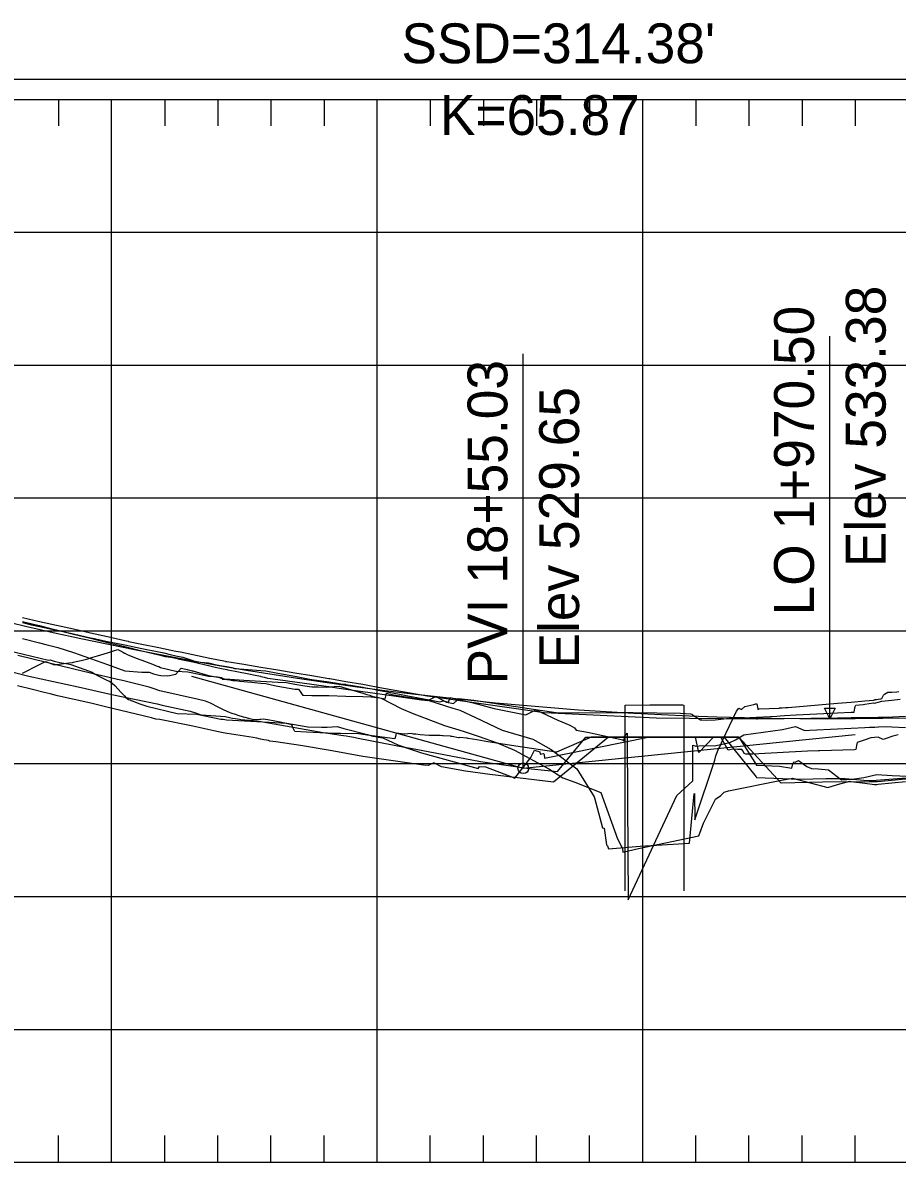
# Model space of a CAD drawing. Extents: x 704834 to 709892, y 372981 to 377533.
# Drawn here: x 706867 to 707196.3, y 375272.4 to 375701.3 of the extents above; entities that cross this region are included whole.
import ezdxf

# ---------------------------------------------------------------- set-up
doc = ezdxf.new("R2010")
doc.units = 0
for name, color, linetype in [('1', 7, 'Continuous'), ('10', 7, 'Continuous'), ('12', 7, 'Continuous'), ('13', 7, 'Continuous'), ('20', 7, 'Continuous'), ('42', 7, 'Continuous'), ('49', 7, 'Continuous'), ('59', 7, 'Continuous'), ('61', 7, 'Continuous'), ('63', 7, 'Continuous'), ('Default_Profile', 7, 'Continuous'), ('Existing', 7, 'Continuous')]:
    doc.layers.add(name, color=color, linetype=linetype)

msp = doc.modelspace()

# ---------------------------------------------------------------- linework, layer by layer
at = {"layer": '1'}
for p, q in [((706930.44, 375455.38), (707055.44, 375420.71)), ((707055.44, 375420.71), (707180.44, 375433.47))]:
    msp.add_line(p, q, dxfattribs=at)
at = {"layer": '10'}
for points in [[(706860.99, 375465.14), (706876.59, 375461.44), (706877.24, 375461.49), (706878.79, 375460.97), (706880.89, 375460.48), (706883.98, 375460.02), (706885.07, 375459.78), (706893.13, 375456.84), (706894.01, 375456.3), (706895.56, 375455.39), (706897.16, 375454.57), (706898.85, 375453.8), (706899.66, 375453.49), (706900.6, 375452.8), (706900.61, 375452.8), (706901.6, 375451.83), (706901.73, 375451.71), (706902.73, 375450.65), (706902.91, 375450.48), (706903.89, 375449.38), (706904.6, 375448.57), (706905.23, 375448.01), (706905.8, 375447.39), (706906.76, 375446.58), (706907.37, 375446.41), (706907.76, 375446.25), (706908.19, 375446.06), (706911.08, 375445.01), (706913.73, 375444.04), (706925.13, 375441.35), (706932.54, 375441.02), (706941.51, 375439.24), (706941.75, 375439.15), (706942.48, 375439.15), (706943.64, 375438.96), (706966.39, 375437.68), (706974.29, 375436.35), (706974.38, 375436.33), (706979.42, 375436.2), (706981.63, 375436.12), (706985.3, 375436.46), (706987.8, 375435.69), (706996.74, 375433.37), (706997.63, 375433.2), (706998.28, 375432.94), (706998.8, 375432.82), (706999.76, 375432.68), (707000.74, 375432.44), (707002.51, 375432.11), (707008.22, 375429.47), (707013.76, 375427.63), (707017.09, 375426.56), (707029.47, 375423.1), (707034.29, 375421.8), (707038.41, 375420.66), (707038.9, 375421.43), (707041.21, 375421.24), (707050.73, 375417.58), (707052.3, 375416.96), (707058.28, 375424.76), (707059.63, 375427.58), (707061.63, 375426.91), (707061.8, 375426.02), (707063.06, 375426.25), (707063.2, 375426.13), (707063.3, 375425.92), (707063.45, 375424.53), (707102.5, 375432.45), (707136.6, 375432.45), (707143.22, 375421.86), (707151.88, 375421.55), (707156.51, 375420.78), (707156.9, 375422.41), (707157.31, 375423.1), (707157.86, 375423), (707159.13, 375423.61), (707162.21, 375421.35), (707163.94, 375420.6), (707166.48, 375420.52), (707170.37, 375420.1), (707175.25, 375416.32), (707179.3, 375416.66), (707183.63, 375417.26), (707188.52, 375418.39), (707194.35, 375417.95), (707211.49, 375417.2)], [(707196.62, 375433.32), (707194.65, 375432.74), (707191.76, 375431.83), (707190.91, 375431.58), (707189.06, 375432.41), (707186.36, 375432.18), (707183.84, 375431.31), (707181.2, 375430.39), (707180.98, 375429.29), (707180.69, 375427.81), (707180.11, 375427.59), (707167.08, 375427.3), (707166.56, 375427.29), (707162.41, 375427.16), (707141.92, 375426.06), (707139.28, 375425.98), (707138.62, 375426.23), (707138.57, 375426.25), (707138.26, 375427.13), (707137.75, 375427.76), (707136.23, 375427.82), (707134.77, 375427.84), (707134.33, 375427.85), (707133.22, 375427.67), (707132.59, 375427.57), (707129.8, 375432.45), (707129.25, 375432.45), (707128.72, 375432.45), (707128.22, 375432.45), (707127.85, 375432.45), (707127.75, 375432.45), (707127.06, 375432.45), (707121.61, 375426.67), (707120.24, 375432.45), (707118.71, 375432.45), (707117.99, 375432.45), (707117.26, 375432.45), (707115.06, 375432.45), (707105.53, 375432.45), (707090.9, 375432.45), (707081.04, 375432.45), (707067.91, 375426.8), (707067.86, 375426.8), (707052.68, 375429.08), (707041.35, 375430.8), (707040.76, 375430.89), (707037.99, 375431.39), (707034.7, 375431.95), (707034.61, 375431.96), (707034.37, 375432), (707031.42, 375432.29), (707031.19, 375432.11), (707031.05, 375432.12), (707028.68, 375432.67), (707028.33, 375432.7), (707028.05, 375432.74), (707025.3, 375432.88), (707025.17, 375432.9), (707025.08, 375432.92), (707024.13, 375433.01), (707023.75, 375433.01), (707022.18, 375433.02), (707022.07, 375433.02), (707020.01, 375433.03), (707016.59, 375433.35), (707015.01, 375433.52), (707014.11, 375433.6), (707013.24, 375433.76), (707010.72, 375433.58), (707010.54, 375433.58), (707007.62, 375433.94), (707007.27, 375432.66), (707007.01, 375431.85), (706996.65, 375433.19), (706993.36, 375433.62), (706986.56, 375433.76), (706985.89, 375433.75), (706984.97, 375433.76), (706983.66, 375433.79), (706981.76, 375433.87), (706978.82, 375434), (706973.82, 375434.26), (706969.39, 375434.5), (706969.12, 375435.11), (706968.79, 375435.75), (706968.32, 375437.01), (706964.56, 375437.89), (706959.3, 375438.92), (706957.47, 375439.13), (706956.61, 375439.12), (706956.28, 375439.11), (706953.98, 375438.95), (706953.45, 375439.06), (706952.93, 375439.23), (706950.74, 375439.76), (706950.14, 375439.98), (706948.11, 375440.55), (706947.46, 375440.8), (706945.48, 375441.44), (706944.81, 375441.72), (706942.77, 375442.61), (706940.49, 375443.7), (706937.7, 375445.19), (706935.83, 375445.99), (706933.19, 375446.53), (706918.54, 375449.9), (706917.77, 375450.13), (706916.77, 375450.49), (706914.6, 375451.21), (706904.52, 375453.76), (706902.65, 375454.17), (706899.43, 375454.82), (706895.09, 375455.85), (706886.22, 375457.98), (706865.07, 375463.11)]]:
    msp.add_lwpolyline(points, dxfattribs=at)
at = {"layer": '12'}
msp.add_lwpolyline([(706851.88, 375459.74), (706869.18, 375455.39), (706887.84, 375451.35), (706900.49, 375448.46), (706917.52, 375444.97), (706919.45, 375444.47), (706929.96, 375442.21), (706932.06, 375441.52), (706934.06, 375440.81), (706934.28, 375440.8), (706943.22, 375440.18), (706944.76, 375439.82), (706945.95, 375439.59), (706946.96, 375439.42), (706947.81, 375439.29), (706948.52, 375439.15), (706949.11, 375439.01), (706955.26, 375438.58), (706980.03, 375434.14), (706985.24, 375433.37), (706985.93, 375433.29), (706986.75, 375433.18), (706987.69, 375433.03), (706988.78, 375432.86), (706990.08, 375432.63), (706991.57, 375432.36), (706993.27, 375432.04), (707010.71, 375428.7), (707012.24, 375428.41), (707014.41, 375428), (707025.52, 375425.9), (707039.29, 375423.27), (707049.88, 375421.8), (707058.5, 375420.54), (707068.33, 375419.53), (707079.04, 375432.45), (707079.91, 375432.45), (707102.93, 375432.45), (707104.7, 375432.45), (707131.11, 375432.45), (707143.08, 375417.46), (707143.29, 375417.29), (707159.6, 375416.64), (707169.37, 375416.85), (707176.5, 375416.89), (707176.64, 375416.89), (707183.63, 375416.18), (707186.7, 375416.1), (707209.3, 375417.89)], dxfattribs=at)
at = {"layer": '13'}
msp.add_lwpolyline([(707204.83, 375417.14), (707188.84, 375415.61), (707185.75, 375415.59), (707168.16, 375415.48), (707152.53, 375415.06), (707136.61, 375432.45), (707128.3, 375432.45), (707118.97, 375432.45), (707114.72, 375432.45), (707113.37, 375432.45), (707107.84, 375432.45), (707095.85, 375432.45), (707087.51, 375432.45), (707066.87, 375415.54), (707042.89, 375418.32), (707033.69, 375419.65), (707024.67, 375421.24), (707021.72, 375422.74), (707019.57, 375421.73), (707017.9, 375421.89), (706994.96, 375425.2), (706982.69, 375427.36), (706971.49, 375429.29), (706962.28, 375430.65), (706960.01, 375430.94), (706959.44, 375431.1), (706958.7, 375431.26), (706957.69, 375431.47), (706956.46, 375431.71), (706955.09, 375431.98), (706953.71, 375432.26), (706943.92, 375433.76), (706942.36, 375434.1), (706940.71, 375434.47), (706938.92, 375434.86), (706931.04, 375436.58), (706918.59, 375439.01), (706917.04, 375439.2), (706915.42, 375439.63), (706898.08, 375443.83), (706892.65, 375445.18), (706880.07, 375447.95), (706877.23, 375448.68), (706875.04, 375449.24), (706870.1, 375450.5), (706864.99, 375451.78)], dxfattribs=at)
at = {"layer": '42'}
for p, q in [((707170.9, 375439.37), (707170.9, 375583.37)), ((707055.44, 375420.71), (707055.44, 375576.71))]:
    msp.add_line(p, q, dxfattribs=at)
for points in [[(706819.3, 375680.05), (707291.58, 375680.05)], [(706857.52, 375476.64), (706867.94, 375474.2), (706878.35, 375471.85), (706888.77, 375469.57), (706899.19, 375467.38), (706909.6, 375465.28), (706920.02, 375463.25), (706930.44, 375461.31), (706940.85, 375459.45), (706951.27, 375457.67), (706961.69, 375455.98), (706972.1, 375454.36), (706982.52, 375452.83), (706992.94, 375451.39), (707003.35, 375450.02), (707013.77, 375448.74), (707024.19, 375447.54), (707034.6, 375446.42), (707045.02, 375445.38), (707065.85, 375443.55), (707076.27, 375442.76), (707086.69, 375442.06), (707097.1, 375441.43), (707107.52, 375440.89), (707117.94, 375440.43), (707128.35, 375440.05), (707138.77, 375439.76), (707149.19, 375439.55), (707159.6, 375439.42), (707170.02, 375439.37), (707180.44, 375439.4), (707190.85, 375439.52), (707201.27, 375439.72)]]:
    msp.add_lwpolyline(points, dxfattribs=at)
msp.add_lwpolyline([(707170.9, 375439.37), (707168.9, 375443.37), (707172.9, 375443.37)], close=True, dxfattribs=at)
msp.add_circle((707055.44, 375420.71), 2, dxfattribs=at)
at = {"layer": '59'}
msp.add_lwpolyline([(707093.82, 375374.52), (707093.83, 375425.31), (707093.84, 375444.52), (707103.12, 375444.61), (707104.84, 375444.62), (707115.44, 375444.53), (707115.8, 375444.52), (707115.85, 375444.52), (707115.85, 375444.16), (707115.87, 375374.52)], dxfattribs=at)
at = {"layer": '61'}
for p, q in [((706700.4, 375672.45), (709300.4, 375672.45)), ((706880.4, 375672.45), (706880.4, 375662.45)), ((706900.4, 375272.45), (706900.4, 375672.45)), ((706920.4, 375672.45), (706920.4, 375662.45)), ((706940.4, 375672.45), (706940.4, 375662.45)), ((706960.4, 375672.45), (706960.4, 375662.45)), ((706980.4, 375672.45), (706980.4, 375662.45)), ((707000.4, 375272.45), (707000.4, 375672.45)), ((707020.4, 375672.45), (707020.4, 375662.45)), ((707040.4, 375672.45), (707040.4, 375662.45)), ((707060.4, 375672.45), (707060.4, 375662.45)), ((707080.4, 375672.45), (707080.4, 375662.45)), ((707100.4, 375272.45), (707100.4, 375672.45)), ((707120.4, 375672.45), (707120.4, 375662.45)), ((707140.4, 375672.45), (707140.4, 375662.45)), ((707160.4, 375672.45), (707160.4, 375662.45)), ((707180.4, 375672.45), (707180.4, 375662.45)), ((706700.4, 375622.45), (709300.4, 375622.45)), ((706700.4, 375572.45), (709300.4, 375572.45)), ((706700.4, 375522.45), (709300.4, 375522.45)), ((706700.4, 375472.45), (709300.4, 375472.45)), ((706700.4, 375422.45), (709300.4, 375422.45)), ((706700.4, 375372.45), (709300.4, 375372.45)), ((706700.4, 375322.45), (709300.4, 375322.45)), ((706880.4, 375272.45), (706880.4, 375282.45)), ((706920.4, 375272.45), (706920.4, 375282.45)), ((706940.4, 375272.45), (706940.4, 375282.45)), ((706960.4, 375272.45), (706960.4, 375282.45)), ((706980.4, 375272.45), (706980.4, 375282.45)), ((707020.4, 375272.45), (707020.4, 375282.45)), ((707040.4, 375272.45), (707040.4, 375282.45)), ((707060.4, 375272.45), (707060.4, 375282.45)), ((707080.4, 375272.45), (707080.4, 375282.45)), ((707120.4, 375272.45), (707120.4, 375282.45)), ((707140.4, 375272.45), (707140.4, 375282.45)), ((707160.4, 375272.45), (707160.4, 375282.45)), ((707180.4, 375272.45), (707180.4, 375282.45)), ((706700.4, 375272.45), (709300.4, 375272.45))]:
    msp.add_line(p, q, dxfattribs=at)
at = {"layer": '63'}
for points in [[(706866.88, 375476.01), (706871.47, 375474.86), (706873.29, 375474.39), (706877.95, 375473.19), (706879.7, 375472.75), (706884.58, 375471.5), (706886.1, 375471.16), (706888.23, 375470.7), (706892.51, 375469.63), (706895.29, 375468.94), (706898.92, 375468.06), (706905.33, 375466.51), (706911.74, 375464.95), (706918.14, 375463.39), (706918.29, 375463.35), (706920.52, 375462.76), (706922.66, 375462.49), (706924.55, 375462.11), (706925.94, 375461.83), (706930.96, 375460.72), (706936.9, 375459.38), (706937.37, 375459.28), (706939.46, 375458.81), (706941.85, 375458.27), (706943.78, 375457.84), (706944.14, 375457.75), (706946.89, 375457.31), (706949.46, 375456.78), (706950.18, 375456.63), (706952.06, 375456.24), (706954.45, 375455.75), (706956.44, 375455.33), (706956.59, 375455.29), (706957.92, 375454.97), (706959.08, 375454.64), (706963, 375454.1), (706969.41, 375453.22), (706975.81, 375452.33), (706982.03, 375451.45), (706982.22, 375451.42), (706982.73, 375451.34), (706983.57, 375451.19), (706988.63, 375450.49), (706995.04, 375449.6), (707001.45, 375448.71), (707017.1, 375446.46), (707019.45, 375446.23), (707022.45, 375447.66), (707026.56, 375445.57), (707029.12, 375445.12), (707030.46, 375446.18), (707031.04, 375446.92), (707036.8, 375446.35), (707037.72, 375446.23), (707039.32, 375445.98), (707061.82, 375442.57), (707067.85, 375441.66), (707067.87, 375441.66), (707072.88, 375441.58), (707092.7, 375441.7), (707096.87, 375441.74), (707114.69, 375441.49), (707118.39, 375441.26), (707118.76, 375441.1), (707118.88, 375441.06), (707119.19, 375440.88), (707122.15, 375438.99), (707122.73, 375438.95), (707124.55, 375438.79), (707127.75, 375438.99), (707133.06, 375439.53), (707140.78, 375439.84), (707150.86, 375440.36), (707152.21, 375440.48), (707153.8, 375440.55), (707158.25, 375440.85), (707173.76, 375441.58), (707178.88, 375441.82), (707179.03, 375441.83), (707179.98, 375441.86), (707180.26, 375443.28), (707180.45, 375443.96), (707180.62, 375444.44), (707183.42, 375444.73), (707184, 375444.82), (707187.35, 375445.28), (707187.57, 375445.2), (707188.21, 375445.4), (707189.12, 375445.61), (707190.52, 375445.94), (707194.24, 375446.33), (707197.38, 375446.66)], [(706866.88, 375475.57), (706870.23, 375474.72), (706873.29, 375474.05), (706879.7, 375472.65), (706886.1, 375471.25), (706892.51, 375469.86), (706893.99, 375469.54), (706898.72, 375468.46), (706898.92, 375468.42), (706905.33, 375467.11), (706911.74, 375465.8), (706918.14, 375464.49), (706920.06, 375464.1), (706922.41, 375463.5), (706924.55, 375463.04), (706927.22, 375462.47), (706929.81, 375461.64), (706930.96, 375461.24), (706932.25, 375460.79), (706936.87, 375460.45), (706937.37, 375460.32), (706939.29, 375459.82), (706941.24, 375459.41), (706942.94, 375459.11), (706943.78, 375458.96), (706944.4, 375458.85), (706945.64, 375458.6), (706946.69, 375458.32), (706950.18, 375458.04), (706956.59, 375457.51), (706958.45, 375457.37), (706963, 375456.52), (706969.41, 375455.33), (706975.01, 375454.29), (706975.81, 375454.17), (706982.22, 375453.2), (706985.36, 375452.72), (706986.78, 375452.54), (706988.46, 375452.31), (706988.63, 375452.28), (706990.42, 375452.01), (706992.69, 375451.63), (706995.04, 375451.22), (706995.42, 375451.15), (706998.56, 375450.57), (707001.45, 375450.02), (707002.19, 375449.88), (707008.85, 375448.61), (707011.91, 375448.02), (707024.03, 375445.69), (707025.39, 375446.03), (707027.23, 375445.56), (707027.95, 375447.4), (707036.58, 375445.3), (707044.49, 375443.16), (707056.37, 375440.78), (707060.21, 375442.73), (707068.39, 375438.84), (707072.92, 375436.99), (707074.69, 375435.97), (707075.37, 375435.06), (707079.64, 375434.35), (707092.95, 375431.44), (707093.39, 375431.02), (707093.52, 375432.62), (707093.6, 375432.94), (707093.76, 375432.94), (707094.55, 375433.94), (707094.71, 375407.99), (707094.88, 375371.25), (707113.23, 375410.45), (707119.28, 375415.96), (707119.34, 375429.46), (707120.15, 375429.15), (707120.44, 375429), (707120.48, 375429), (707122.97, 375429.28), (707127.45, 375429.15), (707133.16, 375430.4), (707135.33, 375431.35), (707138.46, 375433.31), (707153.02, 375435.24), (707157.89, 375436.44), (707157.97, 375436.38), (707161.11, 375434.99), (707161.66, 375434.89), (707163.38, 375435.03), (707173.76, 375435.56), (707178.88, 375435.81), (707184, 375436.05), (707185.82, 375436.13), (707187.15, 375436.14), (707187.81, 375436.15), (707189.12, 375436.34), (707189.17, 375436.35), (707192.33, 375436.4), (707194.24, 375436.32), (707199.36, 375436.08)], [(706866.88, 375469.51), (706873.29, 375467.91), (706875.6, 375467.29), (706879.7, 375466.27), (706880.2, 375466.14), (706886.1, 375464.22), (706892.51, 375462.03), (706898.92, 375459.74), (706905.33, 375457.35), (706905.37, 375457.34), (706911.74, 375456.93), (706912.55, 375456.87), (706914.55, 375456.84), (706916.17, 375456.23), (706918.14, 375455.77), (706918.89, 375455.59), (706921.59, 375455.48), (706924.55, 375456.07), (706924.55, 375456.07), (706926.63, 375458.42), (706928.36, 375458.05), (706928.92, 375457.93), (706930.71, 375457.43), (706930.96, 375457.36), (706936.96, 375455.67), (706937.37, 375455.56), (706937.61, 375455.5), (706940.98, 375454.81), (706941.27, 375454.72), (706941.57, 375454.64), (706941.91, 375454.56), (706943.76, 375454.18), (706943.78, 375454.17), (706944.35, 375454.1), (706946.09, 375453.78), (706947.04, 375453.69), (706948.65, 375453.44), (706950.18, 375453.35), (706950.21, 375453.35), (706951.61, 375453.18), (706953.17, 375453.13), (706954.25, 375453.04), (706956.59, 375452.8), (706958.55, 375452.59), (706961.76, 375451.87), (706963, 375451.66), (706969.41, 375450.54), (706969.45, 375450.53), (706970.78, 375450.52), (706971.65, 375449.25), (706972.16, 375448.45), (706972.24, 375448.28), (706972.76, 375448.26), (706975.81, 375448.16), (706975.81, 375448.16), (706978.01, 375448.13), (706979.63, 375448.15), (706982.22, 375448.08), (706988.63, 375447.89), (706995.04, 375447.71), (706998.15, 375447.61), (707001.45, 375447.17), (707003.42, 375446.89), (707003.81, 375448.3), (707003.96, 375448.96), (707006.51, 375448.35), (707012.86, 375447.32), (707013.61, 375447.21), (707013.87, 375447.15), (707015.55, 375446.91), (707019.85, 375446.23), (707028.9, 375443.33), (707031.49, 375442.57), (707037.47, 375439.83), (707047.53, 375435), (707058.99, 375431.68), (707065.92, 375427.72), (707075.59, 375420.45), (707082.08, 375409.93), (707082.27, 375409.58), (707085.33, 375398.23), (707085.88, 375398.2), (707086.83, 375391.95), (707087.11, 375391.5), (707087.57, 375390.41), (707099.45, 375391.37), (707118.08, 375392.57), (707119.84, 375411.1), (707119.97, 375411.25), (707120.06, 375401.26), (707127.62, 375423.81), (707127.91, 375425.42), (707129.07, 375428.25), (707129.2, 375428.42), (707129.47, 375428.83), (707130.52, 375431.21), (707135.76, 375442.19), (707136.55, 375443.35), (707137.59, 375442.82), (707138.81, 375443.99), (707142.25, 375444.72), (707143, 375444.97), (707143.36, 375444.98), (707143.72, 375443.05), (707143.77, 375442.81), (707144.21, 375443.04), (707151.81, 375443.39), (707151.91, 375443.47), (707152.96, 375443.49), (707154.19, 375443.52), (707155.15, 375443.58), (707173.76, 375445.17), (707178.88, 375445.64), (707184, 375446.1), (707187.35, 375446.39), (707187.7, 375446.47), (707187.78, 375446.5), (707187.95, 375446.53), (707188.42, 375446.61), (707189.12, 375446.72), (707190.14, 375446.87), (707190.4, 375446.91), (707191.09, 375448.23), (707191.44, 375448.56), (707192.71, 375449.36), (707194.24, 375449.4), (707196.1, 375449.43), (707196.92, 375449.58)], [(706866.88, 375456.49), (706873.29, 375459.73), (706875.56, 375460.91), (706878.9, 375459.63), (706879.7, 375459.73), (706884.45, 375460.38), (706885.64, 375460.56), (706886.1, 375460.65), (706887.08, 375460.85), (706888.93, 375461.28), (706891.42, 375461.93), (706892.51, 375462.24), (706895.09, 375462.99), (706898.92, 375464.19), (706901.16, 375464.9), (706902.8, 375465.45), (706903.73, 375464.92), (706904.92, 375464.22), (706905.23, 375464.03), (706905.33, 375463.99), (706906.22, 375463.52), (706906.9, 375463.26), (706909.62, 375462.21), (706911.46, 375461.49), (706911.74, 375461.38), (706915.79, 375459.86), (706917.62, 375459.15), (706918.14, 375458.95), (706918.84, 375458.67), (706924.55, 375457.25), (706924.72, 375457.21), (706929.13, 375456.95), (706930.96, 375456.58), (706936.96, 375455.37), (706937.37, 375455.33), (706940.3, 375455.12), (706941.76, 375454.88), (706941.94, 375454.83), (706942.02, 375454.3), (706943.78, 375454.26), (706944.99, 375454.23), (706950.18, 375453.91), (706956.59, 375453.52), (706963, 375453.14), (706966.29, 375452.94), (706969.41, 375452.41), (706973.18, 375451.77), (706975.81, 375451.39), (706975.89, 375451.38), (706978.2, 375451.31), (706981.17, 375451.21), (706982.22, 375451.31), (706986.07, 375451.66), (706988.63, 375450.87), (706995.04, 375448.92), (706996.58, 375448.45), (706997.64, 375448.18), (706998.17, 375447.93), (706998.51, 375447.85), (706999.03, 375447.76), (707000.21, 375447.5), (707000.98, 375447.29), (707001.45, 375447.19), (707001.94, 375447.09), (707009.49, 375443.17), (707013.62, 375441.51), (707025.73, 375436.76), (707032.85, 375434.62), (707038.49, 375432.78), (707045.57, 375430.34), (707052.17, 375427.52), (707065, 375420.47), (707070.31, 375417.14), (707074.8, 375415.5), (707084.68, 375411.61), (707090.88, 375394.16), (707092.74, 375390.57), (707092.98, 375389.12), (707098.82, 375390.51), (707121.61, 375395.23), (707123.28, 375400.09), (707127.77, 375409.02), (707129.88, 375410.42), (707131.12, 375411.66), (707132.66, 375412.25), (707152.68, 375416.28), (707156.35, 375416.86), (707156.79, 375416.99), (707170.12, 375413.47), (707173.76, 375414.56), (707178.38, 375415.81), (707178.88, 375415.75), (707184, 375415.08), (707187.71, 375414.6), (707188.03, 375414.66), (707188.13, 375414.65), (707188.61, 375414.65), (707189.12, 375414.7), (707194.24, 375415.19), (707199.36, 375415.67)]]:
    msp.add_lwpolyline(points, dxfattribs=at)
at = {"layer": 'Default_Profile'}
msp.add_lwpolyline([(707093.82, 375374.52), (707093.83, 375425.31), (707093.84, 375444.52), (707103.12, 375444.61), (707104.84, 375444.62), (707115.44, 375444.53), (707115.8, 375444.52), (707115.85, 375444.52), (707115.85, 375444.16), (707115.87, 375374.52)], dxfattribs=at)
msp.add_lwpolyline([(707093.82, 375374.52), (707093.83, 375425.31), (707093.84, 375444.52), (707103.12, 375444.61), (707104.84, 375444.62), (707115.44, 375444.53), (707115.8, 375444.52), (707115.85, 375444.52), (707115.85, 375444.16), (707115.87, 375374.52)], dxfattribs=at)
at = {"layer": 'Existing'}
msp.add_lwpolyline([(706866.88, 375477.42), (706873.29, 375476), (706879.7, 375474.56), (706886.1, 375473.13), (706892.51, 375471.69), (706898.92, 375470.25), (706905.33, 375468.8), (706906.6, 375468.51), (706906.76, 375468.47), (706907.29, 375468.34), (706907.34, 375468.33), (706907.39, 375468.32), (706911.74, 375467.44), (706918.14, 375466.15), (706924.55, 375464.84), (706926.35, 375464.48), (706930.96, 375463.52), (706937.37, 375462.19), (706943.31, 375460.97), (706943.34, 375460.96), (706943.36, 375460.95), (706943.61, 375460.93), (706943.78, 375460.9), (706950.18, 375459.84), (706956.59, 375458.78), (706963, 375457.72), (706969.41, 375456.66), (706975.81, 375455.6), (706982.22, 375454.53), (706982.36, 375454.51), (706982.64, 375454.46), (706988.63, 375453.42), (706995.04, 375452.3), (706996.24, 375452.09), (707001.45, 375451.17), (707019.24, 375448.01), (707019.83, 375447.93), (707019.87, 375447.93), (707019.92, 375447.95), (707020, 375447.91), (707020.22, 375447.88), (707063.27, 375441.72), (707105.48, 375439.75), (707105.52, 375439.75), (707105.52, 375439.75), (707105.53, 375439.74), (707143.31, 375439.33), (707143.6, 375439.33), (707143.62, 375439.33), (707173.76, 375439.7), (707178.88, 375439.77), (707184, 375439.83), (707189.12, 375439.89), (707193.65, 375439.93), (707193.8, 375439.94), (707194.24, 375439.98), (707194.63, 375440.02), (707199.36, 375440.27)], dxfattribs=at)

# ---------------------------------------------------------------- texts
at = {"layer": '20'}
for s, p in [("SSD=314.38'", (707009.53, 375686.05)), ('K=65.87', (707024.04, 375659.05))]:
    msp.add_text(s, height=15, dxfattribs=at).set_placement(p)
at = {"layer": '49'}
for s, p in [('Elev 533.38', (707191.9, 375496.39)), ('LO 1+970.50', (707164.9, 375478.23)), ('PVI 18+55.03', (707049.44, 375452.24)), ('Elev 529.65', (707076.44, 375458.25))]:
    msp.add_text(s, height=15, rotation=90, dxfattribs=at).set_placement(p)

doc.saveas('drawing.dxf')
